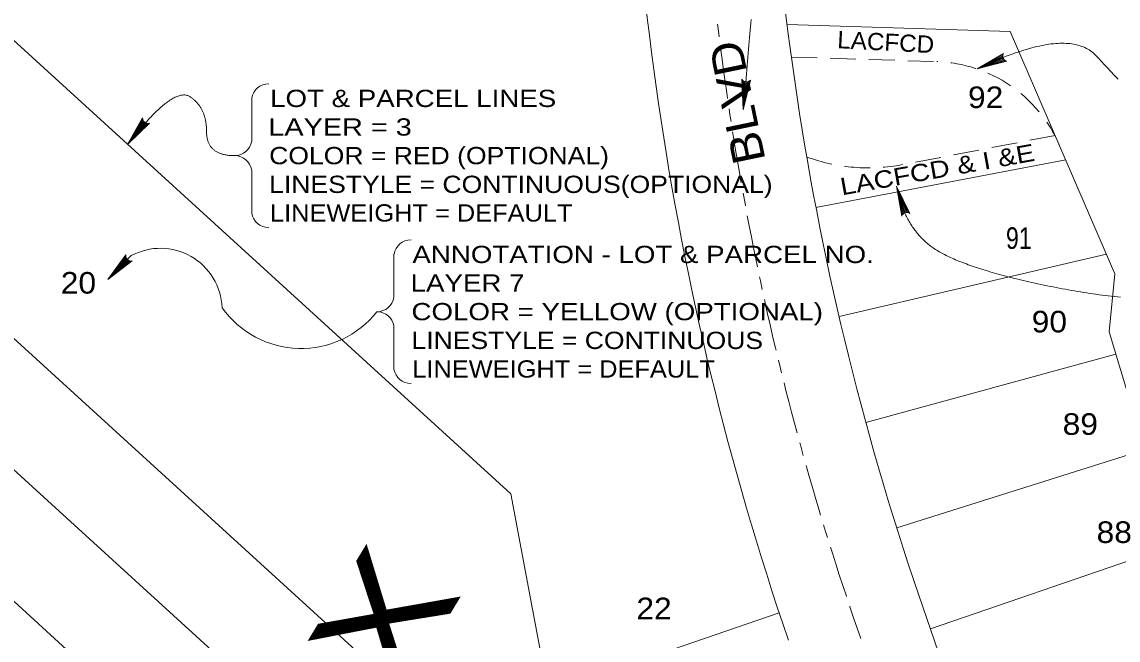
# Model space of a CAD drawing. Extents: x 6387474 to 6390971, y 1972046 to 1973920.
# Drawn here: x 6389237 to 6389745, y 1973251 to 1973538 of the extents above; entities that cross this region are included whole.
import ezdxf

# ---------------------------------------------------------------- set-up
doc = ezdxf.new("R2010")
doc.units = 0
doc.header["$LTSCALE"] = 4
doc.linetypes.add('LONG_DASH_SHORT_DASH', pattern=[9.9, 6, -1.2, 1.5, -1.2])
doc.linetypes.add('MEDIUM_DASHED', pattern=[4.5, 3, -1.5])
for name, color, linetype, lineweight in [('1', 7, 'Continuous', 13), ('2', 7, 'LONG_DASH_SHORT_DASH', 13), ('3', 7, 'Continuous', 13), ('4', 7, 'Continuous', 13), ('5', 7, 'MEDIUM_DASHED', 13), ('8', 7, 'Continuous', 13)]:
    doc.layers.add(name, color=color, linetype=linetype, lineweight=lineweight)
doc.layers.add('7', color=7, linetype='Continuous')

msp = doc.modelspace()

# ---------------------------------------------------------------- hatches: boundary and pattern name
at = {"layer": '8'}
for points in [[(6389679.559, 1973515.816), (6389691.475, 1973522.525), (6389691.709, 1973523.055)], [(6389679.559, 1973515.816), (6389691.369, 1973521.957), (6389691.475, 1973522.525)], [(6389679.559, 1973515.816), (6389691.397, 1973521.379), (6389691.369, 1973521.957)], [(6389691.557, 1973520.823), (6389691.397, 1973521.379), (6389679.559, 1973515.816)], [(6389691.839, 1973520.319), (6389691.557, 1973520.823), (6389679.559, 1973515.816)], [(6389692.231, 1973519.893), (6389691.839, 1973520.319), (6389679.559, 1973515.816)], [(6389692.709, 1973519.569), (6389692.231, 1973519.893), (6389679.559, 1973515.816)], [(6389693.25, 1973519.363), (6389692.709, 1973519.569), (6389679.559, 1973515.816)], [(6389571.007, 1973496.903), (6389570.71, 1973510.575), (6389570.353, 1973511.03)], [(6389571.007, 1973496.903), (6389571.161, 1973510.213), (6389570.71, 1973510.575)], [(6389574.335, 1973510.648), (6389573.899, 1973510.269), (6389571.007, 1973496.903)], [(6389573.899, 1973510.269), (6389573.387, 1973510), (6389571.007, 1973496.903)], [(6389571.007, 1973496.903), (6389571.684, 1973509.965), (6389571.161, 1973510.213)], [(6389573.387, 1973510), (6389572.827, 1973509.856), (6389571.007, 1973496.903)], [(6389572.249, 1973509.844), (6389571.684, 1973509.965), (6389571.007, 1973496.903)], [(6389572.827, 1973509.856), (6389572.249, 1973509.844), (6389571.007, 1973496.903)], [(6389285.462, 1973480.893), (6389292.558, 1973492.583), (6389292.502, 1973493.159)], [(6389285.462, 1973480.893), (6389292.745, 1973492.035), (6389292.558, 1973492.583)], [(6389285.462, 1973480.893), (6389293.052, 1973491.546), (6389292.745, 1973492.035)], [(6389293.463, 1973491.139), (6389293.052, 1973491.546), (6389285.462, 1973480.893)], [(6389293.957, 1973490.839), (6389293.463, 1973491.139), (6389285.462, 1973480.893)], [(6389294.507, 1973490.659), (6389293.957, 1973490.839), (6389285.462, 1973480.893)], [(6389295.655, 1973490.697), (6389295.083, 1973490.611), (6389285.462, 1973480.893)], [(6389295.083, 1973490.611), (6389294.507, 1973490.659), (6389285.462, 1973480.893)], [(6389642.161, 1973461.57), (6389646.704, 1973449.305), (6389647.282, 1973449.283)], [(6389642.161, 1973461.57), (6389647.282, 1973449.283), (6389647.839, 1973449.13)], [(6389642.161, 1973461.57), (6389647.839, 1973449.13), (6389648.347, 1973448.852)], [(6389646.137, 1973449.193), (6389646.704, 1973449.305), (6389642.161, 1973461.57)], [(6389645.61, 1973448.953), (6389646.137, 1973449.193), (6389642.161, 1973461.57)], [(6389645.153, 1973448.6), (6389645.61, 1973448.953), (6389642.161, 1973461.57)], [(6389644.789, 1973448.15), (6389645.153, 1973448.6), (6389642.161, 1973461.57)], [(6389644.538, 1973447.629), (6389644.789, 1973448.15), (6389642.161, 1973461.57)], [(6389276.355, 1973418.235), (6389284.712, 1973429.059), (6389284.72, 1973429.638)], [(6389276.355, 1973418.235), (6389284.836, 1973428.495), (6389284.712, 1973429.059)], [(6389276.355, 1973418.235), (6389285.086, 1973427.974), (6389284.836, 1973428.495)], [(6389285.45, 1973427.524), (6389285.086, 1973427.974), (6389276.355, 1973418.235)], [(6389285.907, 1973427.17), (6389285.45, 1973427.524), (6389276.355, 1973418.235)], [(6389286.434, 1973426.93), (6389285.907, 1973427.17), (6389276.355, 1973418.235)], [(6389287.001, 1973426.818), (6389286.434, 1973426.93), (6389276.355, 1973418.235)], [(6389287.579, 1973426.839), (6389287.001, 1973426.818), (6389276.355, 1973418.235)]]:
    msp.add_hatch(color=256, dxfattribs=at).paths.add_polyline_path(points)

# ---------------------------------------------------------------- linework, layer by layer
at = {"layer": '1'}
for p, q in [((6389694.899, 1973533.165), (6389591.378, 1973536.42)), ((6389743.438, 1973420.866), (6389694.899, 1973533.165)), ((6389740.695, 1973394.066), (6389743.438, 1973420.866)), ((6389875.293, 1972944.722), (6389740.695, 1973394.066))]:
    msp.add_line(p, q, dxfattribs=at)
at = {"layer": '2'}
msp.add_line((6389702.592, 1973027.135), (6389622.235, 1973261.523), dxfattribs=at)
msp.add_arc((6390899.27, 1973699.338), 1350, 170.57423, 198.92361, dxfattribs=at)
at = {"layer": '3'}
for p, q in [((6389463.195, 1973318.918), (6389211.423, 1973548.368)), ((6389461.63, 1973182.312), (6389072.673, 1973536.784)), ((6389431.586, 1973148.835), (6389073.043, 1973475.589)), ((6389604.771, 1973451.562), (6389720.593, 1973473.719)), ((6389615.454, 1973401.116), (6389739.518, 1973429.936)), ((6389401.274, 1973115.575), (6389073.413, 1973414.367)), ((6389627.848, 1973352.05), (6389743.794, 1973383.721)), ((6389642.202, 1973303.229), (6389757.063, 1973339.423)), ((6389479.969, 1973230.272), (6389463.195, 1973318.918)), ((6389770.394, 1973294.917), (6389657.843, 1973256.331)), ((6389587.696, 1973263.794), (6389480.831, 1973227.157))]:
    msp.add_line(p, q, dxfattribs=at)
at = {"layer": '4'}
msp.add_line((6389732.862, 1973037.513), (6389652.505, 1973271.901), dxfattribs=at)
for radius, start in [(1382, 177.67854), (1318, 177.56575)]:
    msp.add_arc((6390899.27, 1973699.338), radius, start, 198.92361, dxfattribs=at)
at = {"layer": '5'}
for p, q in [((6389593.344, 1973521.348), (6389660.87, 1973519.224)), ((6389715.713, 1973485.009), (6389644.976, 1973471.477))]:
    msp.add_line(p, q, dxfattribs=at)
for centre, radius, start, end in [((6389658.859, 1973455.256), 64, 23.37409, 88.19889), ((6389629.193, 1973553.981), 84, 250.04716, 280.83)]:
    msp.add_arc(centre, radius, start, end, dxfattribs=at)
at = {"layer": '8'}
for p, q in [((6389343.077, 1973502.286), (6389343.077, 1973482.306)), ((6389343.077, 1973449), (6389343.077, 1973468.98)), ((6389276.355, 1973418.235), (6389287.199, 1973429.31)), ((6389409.075, 1973429.973), (6389409.075, 1973409.993)), ((6389409.075, 1973376.687), (6389409.075, 1973396.667))]:
    msp.add_line(p, q, dxfattribs=at)
for points in [[(6389574.64, 1973538.824), (6389574.517, 1973537.174), (6389574.389, 1973535.504), (6389574.257, 1973533.804), (6389574.121, 1973532.084), (6389573.982, 1973530.334), (6389573.838, 1973528.554), (6389573.691, 1973526.764), (6389573.539, 1973524.944), (6389573.384, 1973523.094), (6389573.225, 1973521.224), (6389573.062, 1973519.334), (6389572.895, 1973517.414), (6389572.724, 1973515.474), (6389572.549, 1973513.504), (6389572.37, 1973511.514), (6389572.187, 1973509.504), (6389572, 1973507.464), (6389571.809, 1973505.404), (6389571.615, 1973503.314), (6389571.416, 1973501.204), (6389571.214, 1973499.064), (6389571.007, 1973496.904)], [(6389737.656, 1973518.774), (6389737.187, 1973519.284), (6389736.713, 1973519.794), (6389736.234, 1973520.304), (6389735.751, 1973520.834), (6389735.262, 1973521.354), (6389734.77, 1973521.884), (6389734.264, 1973522.414), (6389733.738, 1973522.914), (6389733.191, 1973523.384), (6389732.624, 1973523.834), (6389732.036, 1973524.254), (6389731.428, 1973524.654), (6389730.798, 1973525.034), (6389730.149, 1973525.384), (6389729.478, 1973525.714), (6389728.787, 1973526.014), (6389728.075, 1973526.294), (6389727.343, 1973526.544), (6389726.59, 1973526.774), (6389725.816, 1973526.974), (6389725.022, 1973527.154), (6389724.207, 1973527.314), (6389723.372, 1973527.444), (6389722.516, 1973527.554), (6389721.639, 1973527.634), (6389720.742, 1973527.684), (6389719.824, 1973527.724), (6389718.885, 1973527.734), (6389717.926, 1973527.714), (6389716.946, 1973527.674), (6389715.946, 1973527.604), (6389714.925, 1973527.514), (6389713.883, 1973527.404), (6389712.821, 1973527.264), (6389711.738, 1973527.094), (6389710.634, 1973526.914), (6389709.51, 1973526.694), (6389708.365, 1973526.464), (6389707.2, 1973526.204), (6389706.014, 1973525.914), (6389704.807, 1973525.604), (6389703.58, 1973525.264), (6389702.332, 1973524.904), (6389701.063, 1973524.524), (6389699.774, 1973524.114), (6389698.464, 1973523.684), (6389697.134, 1973523.224), (6389695.783, 1973522.744), (6389694.411, 1973522.234), (6389693.019, 1973521.704), (6389691.606, 1973521.144), (6389690.172, 1973520.564), (6389688.718, 1973519.964), (6389687.243, 1973519.334), (6389685.748, 1973518.674), (6389684.232, 1973517.994), (6389682.695, 1973517.294), (6389681.138, 1973516.564), (6389679.56, 1973515.814)], [(6389691.709, 1973523.055), (6389679.559, 1973515.816), (6389693.25, 1973519.363)], [(6389744.922, 1973511.034), (6389744.532, 1973511.454), (6389744.138, 1973511.864), (6389743.738, 1973512.284), (6389743.334, 1973512.714), (6389742.925, 1973513.144), (6389742.512, 1973513.584), (6389742.094, 1973514.034), (6389741.671, 1973514.484), (6389741.244, 1973514.934), (6389740.812, 1973515.394), (6389740.375, 1973515.864), (6389739.934, 1973516.334), (6389739.487, 1973516.814), (6389739.037, 1973517.294), (6389738.581, 1973517.784), (6389738.121, 1973518.274), (6389737.656, 1973518.774)], [(6389570.353, 1973511.03), (6389571.007, 1973496.903), (6389574.335, 1973510.648)], [(6389316.063, 1973501.774), (6389315.801, 1973501.984), (6389315.534, 1973502.194), (6389315.262, 1973502.404), (6389314.983, 1973502.604), (6389314.7, 1973502.804), (6389314.41, 1973502.994), (6389314.114, 1973503.174), (6389313.807, 1973503.334), (6389313.491, 1973503.464), (6389313.166, 1973503.574), (6389312.831, 1973503.664), (6389312.486, 1973503.724), (6389312.132, 1973503.764), (6389311.768, 1973503.784), (6389311.394, 1973503.784), (6389311.011, 1973503.754), (6389310.618, 1973503.704), (6389310.216, 1973503.634), (6389309.804, 1973503.534), (6389309.383, 1973503.424), (6389308.952, 1973503.274), (6389308.511, 1973503.114), (6389308.061, 1973502.924), (6389307.601, 1973502.714), (6389307.131, 1973502.484), (6389306.652, 1973502.224), (6389306.164, 1973501.944), (6389305.665, 1973501.644), (6389305.158, 1973501.314), (6389304.64, 1973500.974), (6389304.113, 1973500.604), (6389303.577, 1973500.204), (6389303.03, 1973499.784), (6389302.475, 1973499.344), (6389301.909, 1973498.884), (6389301.334, 1973498.404), (6389300.75, 1973497.894), (6389300.156, 1973497.364), (6389299.552, 1973496.804), (6389298.939, 1973496.224), (6389298.316, 1973495.624), (6389297.683, 1973495.004), (6389297.041, 1973494.354), (6389296.389, 1973493.684), (6389295.728, 1973492.994), (6389295.057, 1973492.284), (6389294.377, 1973491.544), (6389293.687, 1973490.784), (6389292.987, 1973489.994), (6389292.278, 1973489.184), (6389291.559, 1973488.354), (6389290.83, 1973487.504), (6389290.092, 1973486.634), (6389289.345, 1973485.734), (6389288.587, 1973484.814), (6389287.821, 1973483.864), (6389287.044, 1973482.894), (6389286.258, 1973481.904), (6389285.463, 1973480.894)], [(6389322.222, 1973485.164), (6389322.19, 1973485.564), (6389322.166, 1973485.964), (6389322.152, 1973486.374), (6389322.148, 1973486.784), (6389322.145, 1973487.204), (6389322.137, 1973487.614), (6389322.123, 1973488.024), (6389322.104, 1973488.434), (6389322.079, 1973488.834), (6389322.049, 1973489.234), (6389322.013, 1973489.624), (6389321.972, 1973490.014), (6389321.925, 1973490.394), (6389321.872, 1973490.774), (6389321.815, 1973491.154), (6389321.751, 1973491.524), (6389321.682, 1973491.884), (6389321.608, 1973492.254), (6389321.528, 1973492.604), (6389321.443, 1973492.964), (6389321.352, 1973493.314), (6389321.255, 1973493.654), (6389321.153, 1973493.994), (6389321.046, 1973494.334), (6389320.933, 1973494.664), (6389320.815, 1973494.994), (6389320.691, 1973495.314), (6389320.561, 1973495.634), (6389320.426, 1973495.944), (6389320.286, 1973496.254), (6389320.14, 1973496.564), (6389319.988, 1973496.864), (6389319.831, 1973497.164), (6389319.669, 1973497.454), (6389319.501, 1973497.744), (6389319.327, 1973498.024), (6389319.148, 1973498.304), (6389318.964, 1973498.584), (6389318.774, 1973498.854), (6389318.578, 1973499.124), (6389318.377, 1973499.384), (6389318.17, 1973499.644), (6389317.958, 1973499.894), (6389317.741, 1973500.144), (6389317.518, 1973500.384), (6389317.289, 1973500.634), (6389317.055, 1973500.864), (6389316.815, 1973501.094), (6389316.57, 1973501.324), (6389316.319, 1973501.554), (6389316.063, 1973501.774)], [(6389292.502, 1973493.159), (6389285.462, 1973480.893), (6389295.655, 1973490.697)], [(6389335.192, 1973475.644), (6389334.704, 1973475.644), (6389334.226, 1973475.654), (6389333.757, 1973475.674), (6389333.297, 1973475.704), (6389332.847, 1973475.744), (6389332.406, 1973475.784), (6389331.974, 1973475.834), (6389331.551, 1973475.894), (6389331.138, 1973475.964), (6389330.734, 1973476.044), (6389330.339, 1973476.124), (6389329.954, 1973476.214), (6389329.578, 1973476.314), (6389329.211, 1973476.424), (6389328.853, 1973476.534), (6389328.505, 1973476.654), (6389328.166, 1973476.794), (6389327.836, 1973476.924), (6389327.516, 1973477.074), (6389327.205, 1973477.234), (6389326.903, 1973477.394), (6389326.61, 1973477.564), (6389326.327, 1973477.744), (6389326.053, 1973477.924), (6389325.788, 1973478.124), (6389325.533, 1973478.324), (6389325.287, 1973478.534), (6389325.05, 1973478.754), (6389324.823, 1973478.984), (6389324.604, 1973479.214), (6389324.395, 1973479.454), (6389324.196, 1973479.704), (6389324.005, 1973479.964), (6389323.824, 1973480.224), (6389323.652, 1973480.504), (6389323.49, 1973480.784), (6389323.337, 1973481.074), (6389323.193, 1973481.374), (6389323.058, 1973481.674), (6389322.933, 1973481.994), (6389322.817, 1973482.314), (6389322.71, 1973482.644), (6389322.612, 1973482.974), (6389322.524, 1973483.324), (6389322.445, 1973483.674), (6389322.375, 1973484.034), (6389322.315, 1973484.404), (6389322.264, 1973484.784), (6389322.222, 1973485.164)], [(6389648.347, 1973448.852), (6389642.161, 1973461.57), (6389644.539, 1973447.629)], [(6389661.922, 1973431.134), (6389661.34, 1973431.484), (6389660.776, 1973431.824), (6389660.229, 1973432.164), (6389659.7, 1973432.514), (6389659.188, 1973432.854), (6389658.694, 1973433.204), (6389658.212, 1973433.554), (6389657.737, 1973433.914), (6389657.268, 1973434.274), (6389656.806, 1973434.644), (6389656.35, 1973435.024), (6389655.901, 1973435.414), (6389655.458, 1973435.804), (6389655.022, 1973436.204), (6389654.592, 1973436.614), (6389654.169, 1973437.024), (6389653.752, 1973437.454), (6389653.342, 1973437.874), (6389652.939, 1973438.314), (6389652.542, 1973438.754), (6389652.152, 1973439.204), (6389651.768, 1973439.664), (6389651.39, 1973440.124), (6389651.02, 1973440.604), (6389650.655, 1973441.074), (6389650.298, 1973441.564), (6389649.946, 1973442.054), (6389649.602, 1973442.554), (6389649.264, 1973443.064), (6389648.932, 1973443.574), (6389648.607, 1973444.094), (6389648.289, 1973444.624), (6389647.977, 1973445.164), (6389647.671, 1973445.704), (6389647.372, 1973446.254), (6389647.08, 1973446.804), (6389646.794, 1973447.374), (6389646.515, 1973447.944), (6389646.242, 1973448.524), (6389645.976, 1973449.104), (6389645.717, 1973449.694), (6389645.464, 1973450.294), (6389645.217, 1973450.904), (6389644.977, 1973451.514), (6389644.744, 1973452.134), (6389644.517, 1973452.764), (6389644.296, 1973453.404), (6389644.082, 1973454.044), (6389643.875, 1973454.694), (6389643.674, 1973455.344), (6389643.48, 1973456.014), (6389643.292, 1973456.684), (6389643.111, 1973457.354), (6389642.937, 1973458.044), (6389642.769, 1973458.734), (6389642.607, 1973459.434), (6389642.452, 1973460.134), (6389642.304, 1973460.854), (6389642.162, 1973461.574)], [(6389714.746, 1973414.784), (6389713.329, 1973415.074), (6389711.913, 1973415.364), (6389710.496, 1973415.654), (6389709.08, 1973415.954), (6389707.673, 1973416.264), (6389706.283, 1973416.564), (6389704.911, 1973416.874), (6389703.556, 1973417.184), (6389702.219, 1973417.484), (6389700.899, 1973417.794), (6389699.597, 1973418.104), (6389698.313, 1973418.414), (6389697.046, 1973418.724), (6389695.797, 1973419.034), (6389694.565, 1973419.354), (6389693.351, 1973419.664), (6389692.155, 1973419.974), (6389690.976, 1973420.294), (6389689.814, 1973420.604), (6389688.67, 1973420.924), (6389687.544, 1973421.244), (6389686.435, 1973421.564), (6389685.344, 1973421.874), (6389684.271, 1973422.194), (6389683.215, 1973422.524), (6389682.176, 1973422.844), (6389681.155, 1973423.164), (6389680.152, 1973423.484), (6389679.166, 1973423.814), (6389678.198, 1973424.134), (6389677.247, 1973424.464), (6389676.314, 1973424.784), (6389675.398, 1973425.114), (6389674.5, 1973425.444), (6389673.62, 1973425.774), (6389672.757, 1973426.094), (6389671.912, 1973426.424), (6389671.084, 1973426.764), (6389670.274, 1973427.094), (6389669.481, 1973427.424), (6389668.706, 1973427.754), (6389667.949, 1973428.094), (6389667.209, 1973428.424), (6389666.487, 1973428.764), (6389665.782, 1973429.104), (6389665.095, 1973429.434), (6389664.425, 1973429.774), (6389663.773, 1973430.114), (6389663.138, 1973430.454), (6389662.521, 1973430.794), (6389661.922, 1973431.134)], [(6389284.72, 1973429.638), (6389276.355, 1973418.235), (6389287.578, 1973426.839)], [(6389745.975, 1973409.994), (6389744.553, 1973410.154), (6389743.131, 1973410.314), (6389741.71, 1973410.484), (6389740.289, 1973410.664), (6389738.868, 1973410.844), (6389737.447, 1973411.024), (6389736.027, 1973411.214), (6389734.606, 1973411.414), (6389733.186, 1973411.624), (6389731.766, 1973411.834), (6389730.347, 1973412.044), (6389728.927, 1973412.264), (6389727.508, 1973412.494), (6389726.089, 1973412.724), (6389724.671, 1973412.964), (6389723.252, 1973413.204), (6389721.834, 1973413.454), (6389720.416, 1973413.714), (6389718.998, 1973413.974), (6389717.581, 1973414.234), (6389716.163, 1973414.514), (6389714.746, 1973414.784)]]:
    msp.add_lwpolyline(points, dxfattribs=at)
for points in [[(6389679.559, 1973515.816), (6389691.475, 1973522.525), (6389691.709, 1973523.055)], [(6389679.559, 1973515.816), (6389691.369, 1973521.957), (6389691.475, 1973522.525)], [(6389679.559, 1973515.816), (6389691.397, 1973521.379), (6389691.369, 1973521.957)], [(6389691.557, 1973520.823), (6389691.397, 1973521.379), (6389679.559, 1973515.816)], [(6389691.839, 1973520.319), (6389691.557, 1973520.823), (6389679.559, 1973515.816)], [(6389692.231, 1973519.893), (6389691.839, 1973520.319), (6389679.559, 1973515.816)], [(6389692.709, 1973519.569), (6389692.231, 1973519.893), (6389679.559, 1973515.816)], [(6389693.25, 1973519.363), (6389692.709, 1973519.569), (6389679.559, 1973515.816)], [(6389571.007, 1973496.903), (6389570.71, 1973510.575), (6389570.353, 1973511.03)], [(6389571.007, 1973496.903), (6389571.161, 1973510.213), (6389570.71, 1973510.575)], [(6389574.335, 1973510.648), (6389573.899, 1973510.269), (6389571.007, 1973496.903)], [(6389573.899, 1973510.269), (6389573.387, 1973510), (6389571.007, 1973496.903)], [(6389571.007, 1973496.903), (6389571.684, 1973509.965), (6389571.161, 1973510.213)], [(6389573.387, 1973510), (6389572.827, 1973509.856), (6389571.007, 1973496.903)], [(6389572.249, 1973509.844), (6389571.684, 1973509.965), (6389571.007, 1973496.903)], [(6389572.827, 1973509.856), (6389572.249, 1973509.844), (6389571.007, 1973496.903)], [(6389285.462, 1973480.893), (6389292.558, 1973492.583), (6389292.502, 1973493.159)], [(6389285.462, 1973480.893), (6389292.745, 1973492.035), (6389292.558, 1973492.583)], [(6389285.462, 1973480.893), (6389293.052, 1973491.546), (6389292.745, 1973492.035)], [(6389293.463, 1973491.139), (6389293.052, 1973491.546), (6389285.462, 1973480.893)], [(6389293.957, 1973490.839), (6389293.463, 1973491.139), (6389285.462, 1973480.893)], [(6389294.507, 1973490.659), (6389293.957, 1973490.839), (6389285.462, 1973480.893)], [(6389295.655, 1973490.697), (6389295.083, 1973490.611), (6389285.462, 1973480.893)], [(6389295.083, 1973490.611), (6389294.507, 1973490.659), (6389285.462, 1973480.893)], [(6389642.161, 1973461.57), (6389646.704, 1973449.305), (6389647.282, 1973449.283)], [(6389642.161, 1973461.57), (6389647.282, 1973449.283), (6389647.839, 1973449.13)], [(6389642.161, 1973461.57), (6389647.839, 1973449.13), (6389648.347, 1973448.852)], [(6389646.137, 1973449.193), (6389646.704, 1973449.305), (6389642.161, 1973461.57)], [(6389645.61, 1973448.953), (6389646.137, 1973449.193), (6389642.161, 1973461.57)], [(6389645.153, 1973448.6), (6389645.61, 1973448.953), (6389642.161, 1973461.57)], [(6389644.789, 1973448.15), (6389645.153, 1973448.6), (6389642.161, 1973461.57)], [(6389644.538, 1973447.629), (6389644.789, 1973448.15), (6389642.161, 1973461.57)], [(6389276.355, 1973418.235), (6389284.712, 1973429.059), (6389284.72, 1973429.638)], [(6389276.355, 1973418.235), (6389284.836, 1973428.495), (6389284.712, 1973429.059)], [(6389276.355, 1973418.235), (6389285.086, 1973427.974), (6389284.836, 1973428.495)], [(6389285.45, 1973427.524), (6389285.086, 1973427.974), (6389276.355, 1973418.235)], [(6389285.907, 1973427.17), (6389285.45, 1973427.524), (6389276.355, 1973418.235)], [(6389286.434, 1973426.93), (6389285.907, 1973427.17), (6389276.355, 1973418.235)], [(6389287.001, 1973426.818), (6389286.434, 1973426.93), (6389276.355, 1973418.235)], [(6389287.579, 1973426.839), (6389287.001, 1973426.818), (6389276.355, 1973418.235)]]:
    msp.add_lwpolyline(points, close=True, dxfattribs=at)
for centre, radius, start, end in [((6389693.864, 1973521.786), 2.5, 149.5258, 255.78601), ((6389350.967, 1973500.949), 8, 90, 170.38048), ((6389572.488, 1973512.332), 2.5, 211.39088, 317.65108), ((6389295.002, 1973493.11), 2.5, 178.88615, 285.14635), ((6389335.191, 1973483.643), 8, 270, 350.38048), ((6389335.191, 1973467.643), 8, 9.61952, 90), ((6389350.966, 1973450.337), 8, 189.61952, 270), ((6389646.901, 1973446.813), 2.5, 54.67709, 160.9373), ((6389416.965, 1973428.636), 8, 90, 170.38048), ((6389300.748, 1973404.139), 28.586, 2.10743, 118.29232), ((6389287.199, 1973429.31), 2.5, 172.47638, 278.73658), ((6389401.189, 1973411.33), 8, 270, 350.38048), ((6389365.95, 1973431.236), 44.951, 215.41016, 321.62389), ((6389401.189, 1973395.33), 8, 9.61952, 90), ((6389416.964, 1973378.024), 8, 189.61952, 270)]:
    msp.add_arc(centre, radius, start, end, dxfattribs=at)

# ---------------------------------------------------------------- texts
at = {"layer": '1', "width": 1.35}
msp.add_text('TR 4321X', height=50, rotation=58.729, dxfattribs=at).set_placement((6389230.058, 1972925.588))
at = {"layer": '2', "width": 1.1}
msp.add_text('BLVD', height=15, rotation=101.744, dxfattribs=at).set_placement((6389581.448, 1973473.593))
at = {"layer": '5'}
for s, rotation, width, p in [('LACFCD', 357.008, 1.05, (6389614.493, 1973525.475)), ('LACFCD & I &E', 10.17, 1.2, (6389616.805, 1973457.232))]:
    msp.add_text(s, height=8, rotation=rotation, dxfattribs=dict(at, width=width)).set_placement(p)
at = {"layer": '7'}
for s, width, p in [('92', 1.1, (6389675.274, 1973497.711)), ('91', 0.8, (6389692.882, 1973432.451)), ('20', 1.1, (6389254.552, 1973411.708)), ('90', 1.1, (6389704.819, 1973393.718)), ('89', 1.1, (6389719.177, 1973346.249)), ('88', 1.1, (6389734.908, 1973296.146)), ('22', 1.1, (6389521.495, 1973260.809))]:
    msp.add_text(s, height=10, dxfattribs=dict(at, width=width)).set_placement(p)
at = {"layer": '8'}
for s, width, p in [('LOT & PARCEL LINES', 1.2, (6389351.611, 1973498.183)), ('LAYER = 3', 1.25, (6389350.799, 1973484.935)), ('COLOR = RED (OPTIONAL)', 1.15, (6389351.191, 1973471.677)), ('LINESTYLE = CONTINUOUS(OPTIONAL)', 1.15, (6389351.191, 1973458.357)), ('LINEWEIGHT = DEFAULT', 1.1, (6389351.583, 1973445.099)), ('ANNOTATION - LOT & PARCEL NO.', 1.2, (6389417.609, 1973425.87)), ('LAYER 7', 1.2, (6389416.797, 1973412.622)), ('COLOR = YELLOW (OPTIONAL)', 1.2, (6389417.189, 1973399.364)), ('LINESTYLE = CONTINUOUS', 1.15, (6389417.189, 1973386.044)), ('LINEWEIGHT = DEFAULT', 1.1, (6389417.581, 1973372.786))]:
    msp.add_text(s, height=8, dxfattribs=dict(at, width=width)).set_placement(p)

doc.saveas('drawing.dxf')
